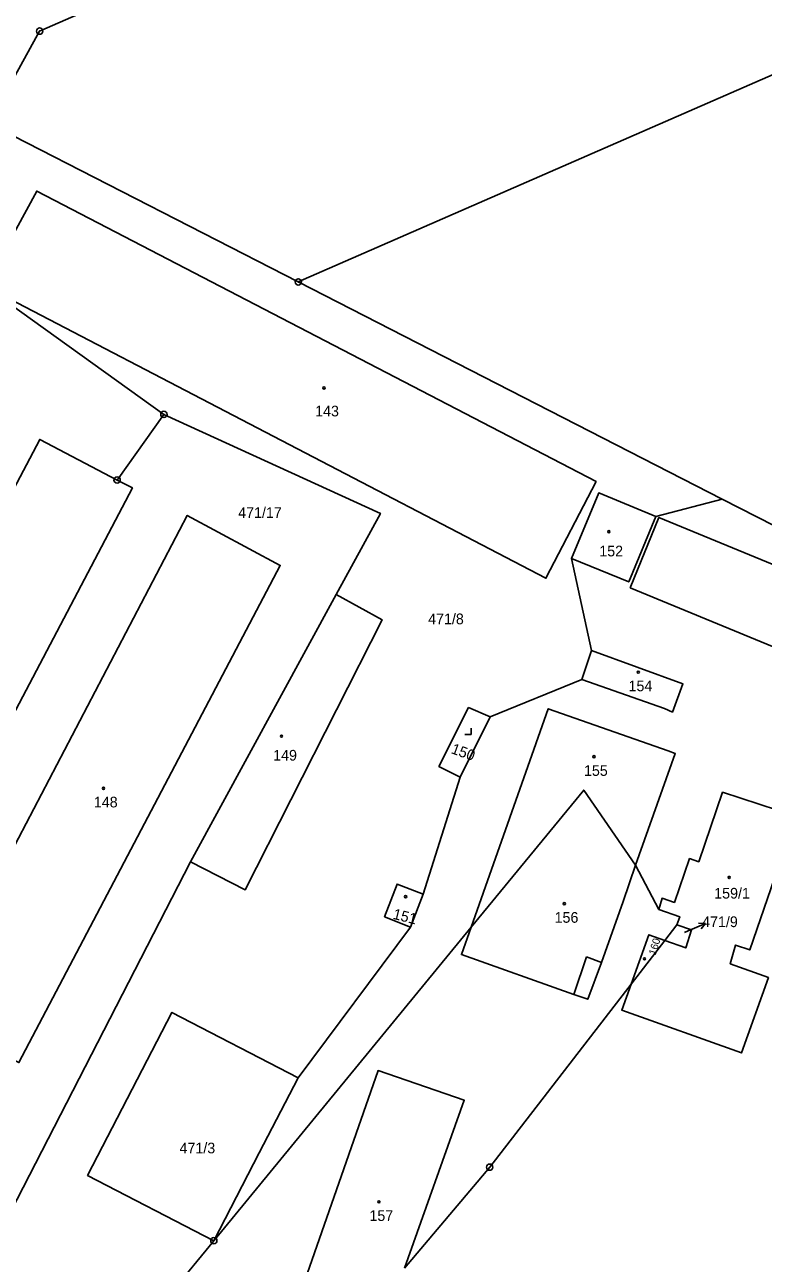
# Model space of a CAD drawing. Extents: x -758582 to -751794, y -998770 to -994350.
# Drawn here: x -753985.8 to -753868, y -996807.6 to -996610.1 of the extents above; entities that cross this region are included whole.
import ezdxf

# ---------------------------------------------------------------- set-up
doc = ezdxf.new("R2010")
doc.units = 0
for name, color, linetype in [('Hranice parcel', 7, 'Continuous'), ('Parcelní čísla', 7, 'Continuous'), ('Pop  PČ popisy', 7, 'Continuous'), ('Vnitřní kresba', 7, 'Continuous'), ('Značky bodu BP', 7, 'Continuous'), ('Značky budov', 7, 'Continuous'), ('Značky kultur', 7, 'Continuous')]:
    doc.layers.add(name, color=color, linetype=linetype)

msp = doc.modelspace()

# ---------------------------------------------------------------- linework, layer by layer
at = {"layer": 'Hranice parcel'}
for p, q in [((-753834.03, -996603.91), (-753942.18, -996651.11)), ((-753987.69, -996627.79), (-753942.18, -996651.11)), ((-753942.18, -996651.11), (-753874.54, -996685.76)), ((-753971.08, -996682.71), (-753963.62, -996672.25)), ((-753885.12, -996688.52), (-753874.54, -996685.76)), ((-753874.54, -996685.76), (-753806.31, -996720.72)), ((-753895.4, -996709.88), (-753898.55, -996695.21)), ((-753936.13, -996700.97), (-753959.36, -996743.62)), ((-753895.4, -996709.88), (-753896.92, -996714.53)), ((-753911.54, -996720.5), (-753896.92, -996714.53)), ((-753916.35, -996730.1), (-753911.54, -996720.5)), ((-753922.23, -996748.76), (-753916.35, -996730.1)), ((-753959.36, -996743.62), (-753990.08, -996803.23)), ((-753884.65, -996751.21), (-753888.35, -996744.13)), ((-753924.25, -996754.03), (-753922.23, -996748.76)), ((-753914.59, -996754.02), (-753955.65, -996804.04)), ((-753942.2, -996778.04), (-753924.25, -996754.03)), ((-753883.67, -996756.15), (-753881.75, -996753.67)), ((-753889.05, -996763.12), (-753883.67, -996756.15)), ((-753955.65, -996804.04), (-753971.59, -996823.37))]:
    msp.add_line(p, q, dxfattribs=at)
for points in [[(-753865.61, -996559.71), (-753983.45, -996611.11), (-753991.86, -996626.34)], [(-753992.17, -996651.81), (-753902.67, -996698.39), (-753894.64, -996682.96), (-753983.91, -996636.61), (-753992.17, -996651.81)], [(-753963.62, -996672.25), (-753992.17, -996651.81), (-753997.97, -996647.39)], [(-753963.62, -996672.25), (-753929.08, -996688.03), (-753936.13, -996700.97)], [(-753971.08, -996682.71), (-753983.44, -996676.24), (-754022.33, -996750.04), (-754019.97, -996751.29)], [(-754019.97, -996751.29), (-754007.56, -996757.92), (-753968.65, -996683.98), (-753971.08, -996682.71)], [(-753885.12, -996688.52), (-753894.24, -996684.76), (-753898.55, -996695.21)], [(-754001.57, -996767.89), (-753986.75, -996775.63), (-753945.06, -996696.33), (-753959.9, -996688.35), (-754001.57, -996767.89)], [(-753898.55, -996695.21), (-753889.44, -996698.97), (-753885.12, -996688.52)], [(-753889.23, -996699.92), (-753830.74, -996723.97), (-753826.13, -996712.75), (-753884.62, -996688.69), (-753889.23, -996699.92)], [(-753959.36, -996743.62), (-753950.63, -996748.06), (-753928.81, -996705), (-753936.13, -996700.97)], [(-753896.92, -996714.53), (-753883.73, -996719.17), (-753882.47, -996719.73), (-753880.8, -996715.21), (-753895.4, -996709.88)], [(-753911.54, -996720.5), (-753914.99, -996719.01), (-753919.74, -996728.4), (-753916.35, -996730.1)], [(-753888.35, -996744.13), (-753882.01, -996726.32), (-753883.14, -996725.92), (-753902.28, -996719.19), (-753914.59, -996754.02)], [(-753914.59, -996754.02), (-753896.63, -996732.17), (-753888.35, -996744.13)], [(-753884.65, -996751.21), (-753884.11, -996749.42), (-753882.15, -996750.09), (-753879.74, -996743.09), (-753878.28, -996743.59), (-753874.47, -996732.5), (-753862.77, -996736.34), (-753870.13, -996757.67), (-753872.4, -996756.89), (-753873.24, -996759.88), (-753867.14, -996762.07), (-753871.44, -996774.09), (-753890.56, -996767.28), (-753889.05, -996763.12)], [(-753914.59, -996754.02), (-753916.14, -996758.41), (-753898.21, -996764.78), (-753895.98, -996765.53), (-753893.77, -996759.66), (-753890.33, -996749.96), (-753888.35, -996744.13)], [(-753922.23, -996748.76), (-753926.41, -996747.16), (-753928.41, -996752.36), (-753924.25, -996754.03)], [(-753881.75, -996753.67), (-753881.3, -996752.36), (-753884.65, -996751.21)], [(-753883.67, -996756.15), (-753886.21, -996755.25), (-753889.05, -996763.12)], [(-753883.67, -996756.15), (-753880.34, -996757.35), (-753879.43, -996754.47), (-753881.75, -996753.67)], [(-753925.2, -996808.41), (-753911.63, -996792.31), (-753889.05, -996763.12)], [(-753942.2, -996778.04), (-753962.35, -996767.62), (-753975.8, -996793.62), (-753955.65, -996804.04)], [(-753925.2, -996808.41), (-753915.7, -996781.65), (-753929.45, -996776.91), (-753948.59, -996831.69), (-753945.68, -996832.7)], [(-753955.65, -996804.04), (-753948.4, -996790.03), (-753942.2, -996778.04)]]:
    msp.add_lwpolyline(points, dxfattribs=at)
at = {"layer": 'Pop  PČ popisy'}
for p, q in [((-753879.94, -996754.61), (-753877.18, -996753.44)), ((-753877.18, -996753.44), (-753878.3, -996753.37)), ((-753877.18, -996753.44), (-753877.9, -996754.29)), ((-753880.56, -996754.87), (-753879.94, -996754.61))]:
    msp.add_line(p, q, dxfattribs=at)
at = {"layer": 'Vnitřní kresba'}
for p in [(-753898.21, -996764.78), (-753893.77, -996759.66)]:
    msp.add_line(p, (-753896.18, -996758.77), dxfattribs=at)
at = {"layer": 'Značky bodu BP'}
for centre, radius in [((-753983.45, -996611.11), 0.5), ((-753983.45, -996611.11), 0.0303), ((-753942.18, -996651.11), 0.5), ((-753942.18, -996651.11), 0.0303), ((-753963.62, -996672.25), 0.5), ((-753963.62, -996672.25), 0.0303), ((-753971.08, -996682.71), 0.5), ((-753971.08, -996682.71), 0.0303), ((-753911.63, -996792.31), 0.5), ((-753911.63, -996792.31), 0.0303), ((-753955.65, -996804.04), 0.5), ((-753955.65, -996804.04), 0.0303)]:
    msp.add_circle(centre, radius, dxfattribs=at)
at = {"layer": 'Značky budov'}
for centre in [(-753938.07, -996668.02), (-753892.61, -996690.94), (-753887.92, -996713.35), (-753944.85, -996723.56), (-753894.99, -996726.85), (-753973.26, -996731.88), (-753873.41, -996746.1), (-753925.05, -996749.16), (-753899.72, -996750.28), (-753886.93, -996759.08), (-753929.31, -996797.84)]:
    msp.add_circle(centre, 0.175, dxfattribs=at)
at = {"layer": 'Značky kultur'}
for p, q in [((-753915.58, -996723.28), (-753914.58, -996723.28)), ((-753914.58, -996723.28), (-753914.58, -996722.28))]:
    msp.add_line(p, q, dxfattribs=at)

# ---------------------------------------------------------------- texts
at = {"layer": 'Parcelní čísla'}
for s, p in [('143', (-753939.48, -996672.56)), ('471/17', (-753951.76, -996688.76)), ('152', (-753894.14, -996694.89)), ('471/8', (-753921.45, -996705.71)), ('154', (-753889.47, -996716.4)), ('149', (-753946.18, -996727.46)), ('155', (-753896.58, -996729.9)), ('148', (-753974.79, -996734.93)), ('159/1', (-753875.8, -996749.47)), ('156', (-753901.27, -996753.33)), ('471/9', (-753877.73, -996754.02)), ('471/3', (-753961.12, -996790.11)), ('157', (-753930.82, -996800.89))]:
    msp.add_text(s, height=1.7, dxfattribs=at).set_placement(p)
for s, height, rotation, p in [('150', 1.7, 340, (-753917.91, -996726.25)), ('151', 1.7, 346, (-753927.19, -996752.68)), ('160', 1.2, 73, (-753885.15, -996758.58))]:
    msp.add_text(s, height=height, rotation=rotation, dxfattribs=at).set_placement(p)

doc.saveas('drawing.dxf')
